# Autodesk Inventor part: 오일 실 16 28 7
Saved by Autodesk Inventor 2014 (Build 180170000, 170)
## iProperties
Created: 2026-10
Part Number: 오일 실 16 28 7
Material: 일반
Document SubType Name: Modeling
Designer: dg
Density: 1 g/cm^3
Appearance: 기본값
Author: dg
Author: jhkim
Description: 오일-실
Creation Date: 2026-09-29
Sending System: Autodesk Inventor 2027
Preprocessor: ST-DEVELOPER v20.1
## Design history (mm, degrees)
node "오일 실 16 28 71"
body "Solid1"
node "기준1"
